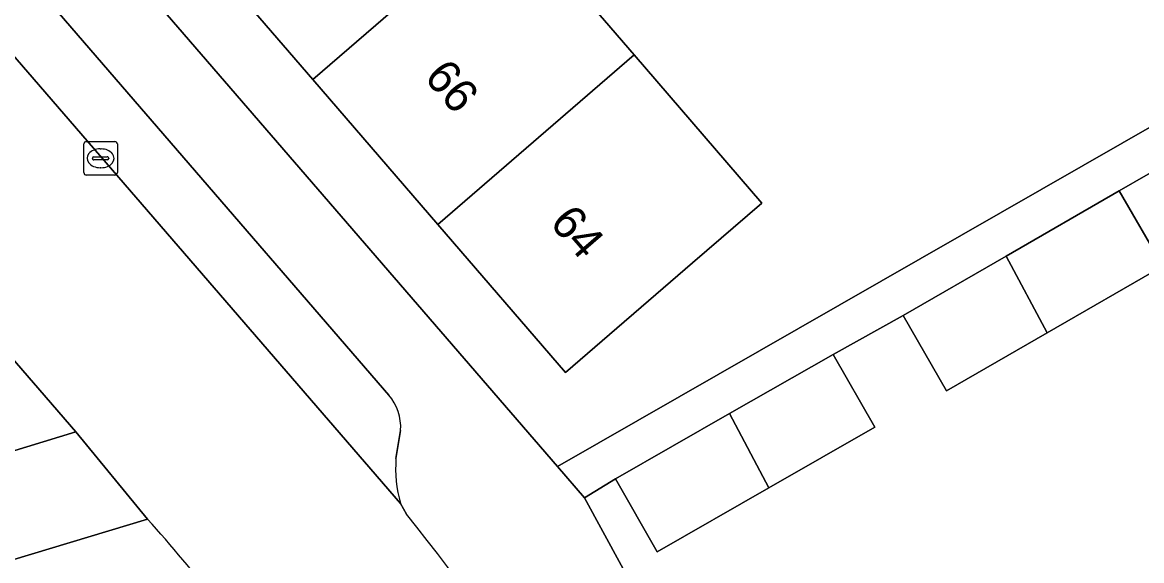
# Model space of a CAD drawing. Extents: x 160304 to 160955, y 383684 to 384161.
# Drawn here: x 160650.22 to 160683.55, y 383941.59 to 383957.6 of the extents above; entities that cross this region are included whole.
import ezdxf

# ---------------------------------------------------------------- set-up
doc = ezdxf.new("R2010")
doc.units = 0
for name, color, linetype in [('IMGEO_Erf', 7, 'Continuous'), ('IMGEO_Groenvoorziening', 7, 'Continuous'), ('IMGEO_Kolk', 7, 'Continuous'), ('IMGEO_Pand', 7, 'Continuous'), ('IMGEO_Pand_nummerreeks', 7, 'Continuous'), ('IMGEO_Parkeervlak_open', 7, 'Continuous'), ('IMGEO_Rijbaan_lokaal_open', 7, 'Continuous'), ('IMGEO_Voetpad_open', 7, 'Continuous')]:
    doc.layers.add(name, color=color, linetype=linetype)

msp = doc.modelspace()

# ---------------------------------------------------------------- linework, layer by layer
at = {"layer": 'IMGEO_Erf'}
for points in [[(160623.685, 383993.483), (160666.156, 383944.39), (160688.992, 383957.451)], [(160664.711, 383960.952), (160668.436, 383956.636), (160672.24, 383952.23), (160670.178, 383950.451), (160666.393, 383947.183), (160662.59, 383951.589), (160658.864, 383955.904), (160655.138, 383960.22)], [(160684.61, 383953.588), (160682.887, 383952.596), (160684.18, 383950.35), (160680.742, 383948.37), (160677.74, 383946.641), (160676.446, 383948.887), (160674.363, 383947.727), (160675.604, 383945.557), (160672.453, 383943.756), (160669.118, 383941.85), (160667.877, 383944.02), (160666.961, 383943.459), (160673.507, 383931.437), (160675.848, 383932.683), (160673.964, 383936.223), (160675.917, 383937.262), (160677.959, 383938.349), (160679.649, 383935.174), (160681.808, 383936.323), (160684.167, 383937.579), (160682.515, 383940.683), (160684.35, 383941.66)]]:
    msp.add_lwpolyline(points, dxfattribs=at)
at = {"layer": 'IMGEO_Groenvoorziening'}
msp.add_lwpolyline([(160635.78, 383963.935), (160633.522, 383961.858), (160629.26, 383952.781), (160639.023, 383941.517), (160651.803, 383945.418), (160648.205, 383949.577)], close=True, dxfattribs=at)
msp.add_lwpolyline([(160653.945, 383942.828), (160640.639, 383938.82), (160655.348, 383911.26)], dxfattribs=at)
msp.add_arc((160592.028, 383888.258), 82.533, 39.16144, 41.39091, dxfattribs=at)
at = {"layer": 'IMGEO_Kolk'}
for p, q in [((160652.119, 383954.061), (160652.971, 383954.061)), ((160652.044, 383953.135), (160652.044, 383953.987)), ((160652.532, 383953.841), (160652.557, 383953.841)), ((160653.045, 383953.987), (160653.045, 383953.135)), ((160652.303, 383953.555), (160652.303, 383953.567)), ((160652.741, 383953.518), (160652.343, 383953.518)), ((160652.346, 383953.604), (160652.744, 383953.604)), ((160652.787, 383953.567), (160652.787, 383953.555)), ((160652.971, 383953.061), (160652.119, 383953.061)), ((160652.555, 383953.281), (160652.53, 383953.281))]:
    msp.add_line(p, q, dxfattribs=at)
for points in [[(160652.119, 383954.061), (160652.971, 383954.061)], [(160652.044, 383953.135), (160652.044, 383953.987)], [(160653.045, 383953.987), (160653.045, 383953.135)], [(160652.971, 383953.061), (160652.119, 383953.061)]]:
    msp.add_lwpolyline(points, dxfattribs=at)
for centre, radius, start, end in [((160652.121, 383953.985), 0.0765, 91.552, 178.448), ((160652.121, 383953.985), 0.0765, 91.552, 178.448), ((160652.969, 383953.985), 0.0765, 1.552, 88.448), ((160652.969, 383953.985), 0.0765, 1.552, 88.448), ((160652.343, 383953.564), 0.0403, 85.8775, 175.7526), ((160652.34, 383953.554), 0.0366, 178.938, 274.7102), ((160652.744, 383953.561), 0.043, 264.8664, 352.4533), ((160652.748, 383953.566), 0.0386, 1.7309, 96.639), ((160652.121, 383953.137), 0.0765, 181.552, 268.448), ((160652.121, 383953.137), 0.0765, 181.552, 268.448), ((160652.969, 383953.137), 0.0765, 271.552, 358.448), ((160652.969, 383953.137), 0.0765, 271.552, 358.448)]:
    msp.add_arc(centre, radius, start, end, dxfattribs=at)
for centre, major_axis, ratio, start_param, end_param in [((160652.531, 383953.561), (-0.387, 0.002), 0.722429, 4.712389, 7.853982), ((160652.556, 383953.561), (-0.39, 0.002), 0.717154, 1.570796, 4.712389)]:
    msp.add_ellipse(centre, major_axis=major_axis, ratio=ratio, start_param=start_param, end_param=end_param, dxfattribs=at)
at = {"layer": 'IMGEO_Pand'}
for points in [[(160658.864, 383955.904), (160664.711, 383960.952), (160660.985, 383965.267), (160655.138, 383960.22)], [(160658.864, 383955.904), (160662.59, 383951.589), (160668.436, 383956.636), (160664.711, 383960.952)], [(160668.436, 383956.636), (160662.59, 383951.589), (160666.393, 383947.183), (160670.178, 383950.451), (160672.24, 383952.23)], [(160682.887, 383952.596), (160679.514, 383950.654), (160680.742, 383948.37), (160684.18, 383950.35)], [(160679.514, 383950.654), (160676.446, 383948.887), (160677.74, 383946.641), (160680.742, 383948.37)], [(160671.276, 383945.963), (160672.453, 383943.756), (160675.604, 383945.557), (160674.363, 383947.727)], [(160671.276, 383945.963), (160667.877, 383944.02), (160669.118, 383941.85), (160672.453, 383943.756)]]:
    msp.add_lwpolyline(points, close=True, dxfattribs=at)
at = {"layer": 'IMGEO_Parkeervlak_open'}
for points in [[(160661.127, 383946.517), (160639.405, 383971.639), (160638.009, 383970.431), (160661.474, 383943.291)], [(160661.341, 383944.625), (160661.481, 383945.463)]]:
    msp.add_lwpolyline(points, dxfattribs=at)
for centre, radius, start, end in [((160660.009, 383945.555), 1.475, 356.422, 40.7086), ((160665.384, 383944.354), 4.052, 176.1727, 195.2145)]:
    msp.add_arc(centre, radius, start, end, dxfattribs=at)
at = {"layer": 'IMGEO_Rijbaan_lokaal_open'}
for points in [[(160638.009, 383970.431), (160634.971, 383967.802), (160640.947, 383960.968), (160649.767, 383950.885), (160648.205, 383949.577), (160651.803, 383945.418), (160653.945, 383942.828)], [(160661.66, 383942.977), (160661.474, 383943.291), (160638.009, 383970.431)]]:
    msp.add_lwpolyline(points, dxfattribs=at)
for centre, radius, start, end in [((160592.028, 383888.258), 82.533, 39.16144, 41.39091), ((160588.303, 383885.017), 93.491, 28.55214, 38.31252)]:
    msp.add_arc(centre, radius, start, end, dxfattribs=at)
at = {"layer": 'IMGEO_Voetpad_open'}
for points in [[(160670.424, 383929.702), (160673.507, 383931.437), (160666.961, 383943.459), (160666.156, 383944.39), (160623.685, 383993.483), (160622.845, 383994.454), (160620.767, 383996.856), (160613.663, 384005.068), (160608.608, 384010.922), (160606.643, 384013.229), (160607.2, 384016.252)], [(160622.749, 383990.925), (160635.052, 383976.673), (160637.593, 383973.734), (160639.405, 383971.639), (160661.127, 383946.517)], [(160655.348, 383911.26), (160640.639, 383938.82), (160653.945, 383942.828), (160651.803, 383945.418), (160639.023, 383941.517), (160629.26, 383952.781), (160617.179, 383966.719)], [(160688.992, 383957.451), (160666.156, 383944.39), (160666.961, 383943.459), (160667.877, 383944.02), (160671.276, 383945.963), (160674.363, 383947.727), (160676.446, 383948.887), (160679.514, 383950.654), (160682.887, 383952.596), (160684.61, 383953.588)], [(160661.481, 383945.463), (160661.341, 383944.625)], [(160661.474, 383943.291), (160661.66, 383942.977)]]:
    msp.add_lwpolyline(points, dxfattribs=at)
for centre, radius, start, end in [((160660.009, 383945.555), 1.475, 356.422, 40.7086), ((160665.384, 383944.354), 4.052, 176.1727, 195.2145), ((160588.303, 383885.017), 93.491, 28.55214, 38.31252)]:
    msp.add_arc(centre, radius, start, end, dxfattribs=at)

# ---------------------------------------------------------------- texts
at = {"layer": 'IMGEO_Pand_nummerreeks'}
for s, p in [('66', (160662.15, 383955.954)), ('64', (160665.89, 383951.621))]:
    msp.add_text(s, height=1, rotation=310.8031, dxfattribs=at).set_placement(p)

doc.saveas('drawing.dxf')
